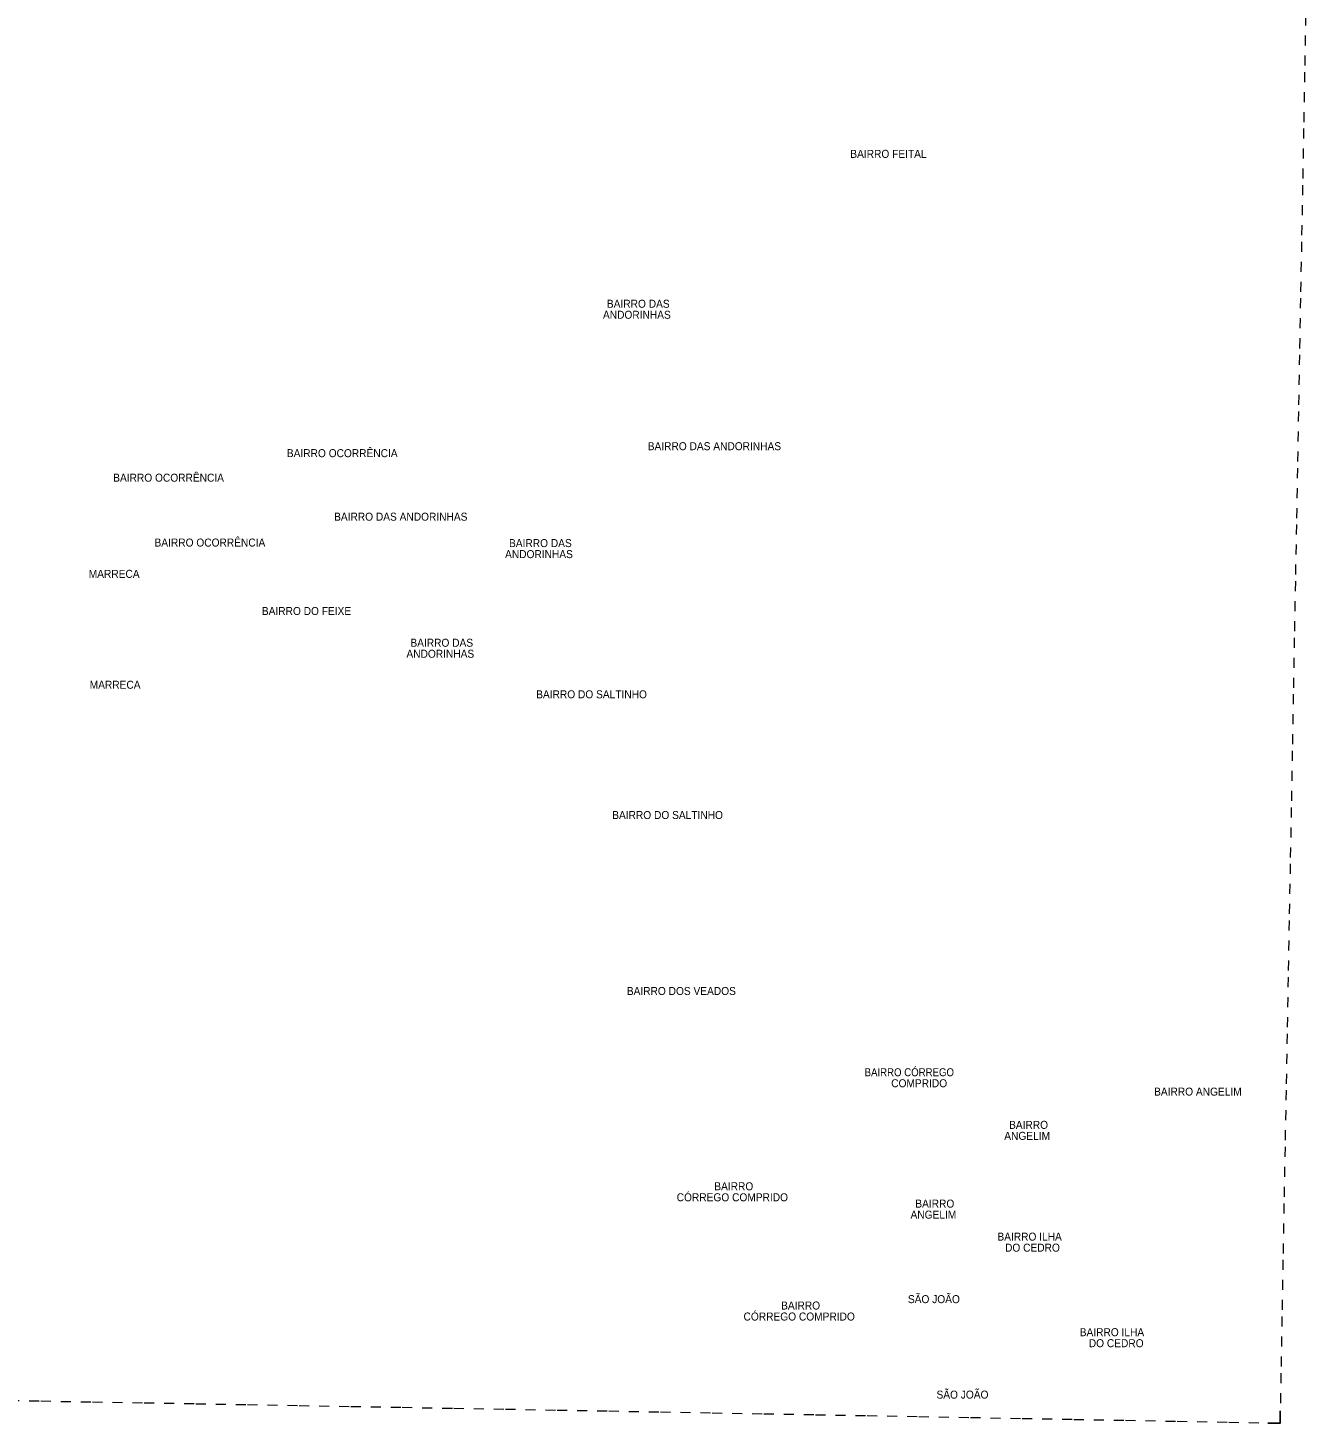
# Model space of a CAD drawing. Extents: x 727.5 to 753.3, y 7260.4 to 7288.5.
# Drawn here: x 740.32 to 753.09, y 7260.41 to 7274.36 of the extents above; entities that cross this region are included whole.
import ezdxf
from ezdxf.enums import TextEntityAlignment as Align

# ---------------------------------------------------------------- set-up
doc = ezdxf.new("R2010")
doc.units = 0
doc.header["$LTSCALE"] = 0.032
doc.linetypes.add('SHORT_DASHED', pattern=[2.7, 1.5, -1.2])
doc.layers.add('46', color=7, linetype='SHORT_DASHED', lineweight=13)
doc.layers.add('63', color=7, linetype='Continuous', lineweight=25)
doc.layers.add('61', color=7, linetype='Continuous')

msp = doc.modelspace()

# ---------------------------------------------------------------- linework, layer by layer
at = {"layer": '46'}
for points in [[(752.8357, 7260.4141), (752.846, 7260.9794), (752.8563, 7261.5447), (752.8667, 7262.1099), (752.877, 7262.6752), (752.8873, 7263.2405), (752.8976, 7263.8058), (752.908, 7264.371), (752.9183, 7264.9363), (752.9286, 7265.5016), (752.9389, 7266.0668), (752.9492, 7266.6321), (752.9595, 7267.1974), (752.9698, 7267.7627), (752.9801, 7268.3279), (752.9904, 7268.8932), (753.0007, 7269.4585), (753.011, 7270.0238), (753.0213, 7270.589), (753.0316, 7271.1543), (753.0419, 7271.7196), (753.0522, 7272.2848), (753.0625, 7272.8501), (753.0728, 7273.4154), (753.0831, 7273.9806), (753.0934, 7274.5459)], [(739.9309, 7260.644), (740.4471, 7260.635), (740.9633, 7260.626), (741.4795, 7260.617), (741.9956, 7260.608), (742.5118, 7260.599), (743.028, 7260.5899), (743.5442, 7260.5808), (744.0604, 7260.5717), (744.5766, 7260.5626), (745.0927, 7260.5535), (745.6089, 7260.5443), (746.1251, 7260.5351), (746.6413, 7260.5259), (747.1575, 7260.5167), (747.6737, 7260.5075), (748.1899, 7260.4982), (748.7061, 7260.489), (749.2223, 7260.4797), (749.7385, 7260.4704), (750.2547, 7260.461), (750.7709, 7260.4517), (751.2871, 7260.4423), (751.8033, 7260.4329), (752.3195, 7260.4235), (752.8357, 7260.4141)]]:
    msp.add_lwpolyline(points, dxfattribs=at)
at = {"layer": '63'}
msp.add_lwpolyline([(752.7125, 7260.4143), (752.8357, 7260.4143), (752.8357, 7260.5357)], dxfattribs=at)

# ---------------------------------------------------------------- texts
at = {"layer": '61'}
for s, width, p in [('BAIRRO FEITAL', 0.95, (748.9192, 7273.0579)), (' BAIRRO DAS', 0.95, (746.4046, 7271.5598)), ('ANDORINHAS', 0.95, (746.40455, 7271.4498)), ('BAIRRO OCORRÊNCIA', 0.95, (743.46005, 7270.0668)), ('BAIRRO DAS ANDORINHAS', 0.95, (747.1796, 7270.1365)), ('BAIRRO OCORRÊNCIA', 0.95, (741.72435, 7269.8216)), ('BAIRRO DAS ANDORINHAS', 0.95, (744.0448, 7269.4319)), ('BAIRRO OCORRÊNCIA', 0.95, (742.13735, 7269.1734)), (' BAIRRO DAS', 0.95, (745.4262, 7269.168)), ('ANDORINHAS', 0.95, (745.42615, 7269.058)), ('MARRECA', 0.95, (741.18035, 7268.8608)), ('BAIRRO DO FEIXE', 0.95, (743.10295, 7268.4895)), ('ANDORINHAS', 0.95, (744.44035, 7268.0622)), (' BAIRRO DAS', 0.95, (744.4404, 7268.1722)), ('MARRECA', 0.95, (741.19005, 7267.7525)), ('BAIRRO DO SALTINHO', 0.95, (745.9518, 7267.657)), ('BAIRRO DO SALTINHO', 0.95, (746.7116, 7266.4506)), ('BAIRRO DOS VEADOS', 0.95, (746.8493, 7264.6921)), ('BAIRRO CÓRREGO', 0.9, (749.12745, 7263.8802)), ('       COMPRIDO', 0.95, (749.12745, 7263.7702)), ('BAIRRO ANGELIM', 0.95, (752.0119, 7263.6866)), (' BAIRRO', 0.95, (750.30525, 7263.3546)), ('ANGELIM', 0.95, (750.30525, 7263.2446)), ('CÓRREGO COMPRIDO', 0.95, (747.35915, 7262.6307)), (' BAIRRO', 0.95, (747.35915, 7262.7407)), (' BAIRRO', 0.95, (749.36845, 7262.5673)), ('ANGELIM', 0.95, (749.36845, 7262.4573)), ('BAIRRO ILHA', 0.95, (750.33005, 7262.2373)), ('  DO CEDRO', 0.95, (750.33015, 7262.1273)), (' BAIRRO', 0.95, (748.02705, 7261.5491)), ('SÃO JOÃO', 0.95, (749.3734, 7261.6128)), ('CÓRREGO COMPRIDO', 0.95, (748.02705, 7261.4391)), ('BAIRRO ILHA ', 0.95, (751.1671, 7261.2826)), ('  DO CEDRO', 0.95, (751.16715, 7261.1726)), ('SÃO JOÃO', 0.95, (749.659, 7260.6587))]:
    msp.add_text(s, height=0.08, dxfattribs=dict(at, width=width)).set_placement(p, align=Align.CENTER)

doc.saveas('drawing.dxf')
